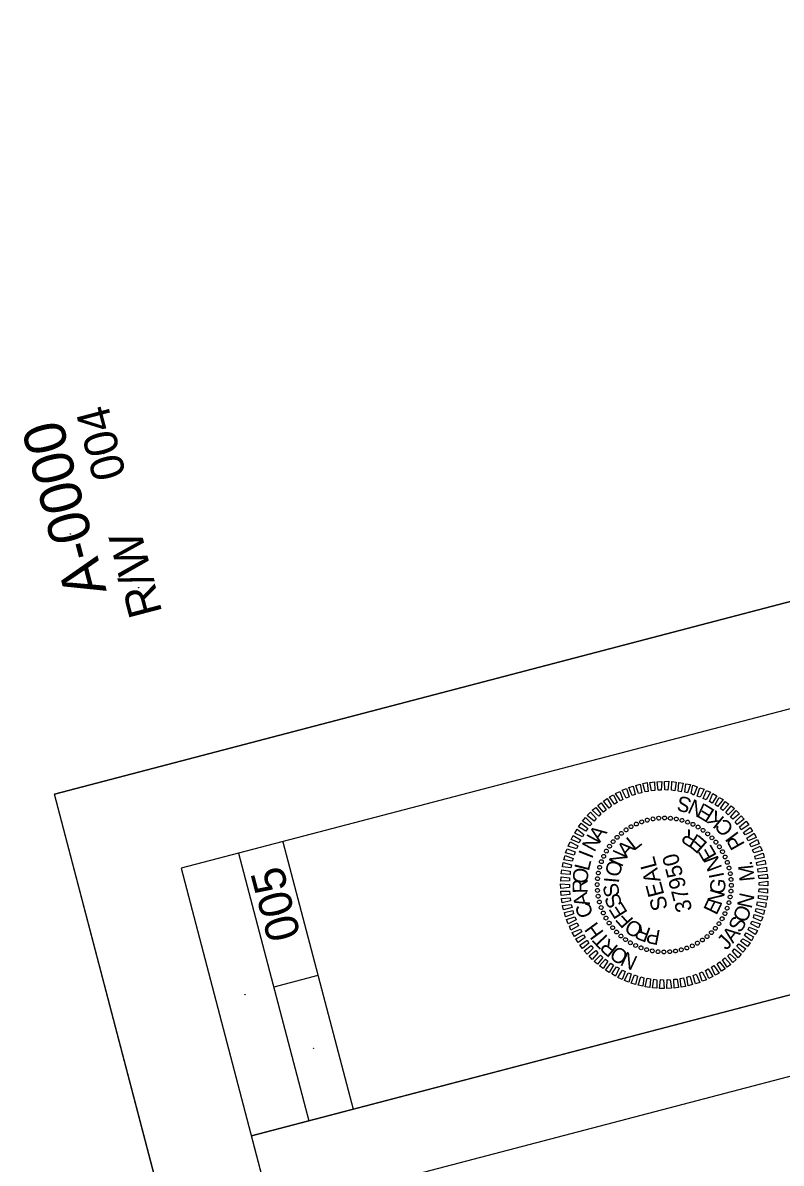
# Model space of a CAD drawing. Extents: x 1366394 to 1367903, y 879298 to 881221.
# Drawn here: x 1366396.1 to 1366670, y 880808.9 to 881221.1 of the extents above; entities that cross this region are included whole.
import ezdxf

# ---------------------------------------------------------------- set-up
doc = ezdxf.new("R2010")
doc.units = 0
for name, color, linetype in [('Exist Property Line Leader', 7, 'Continuous'), ('Exist Property Line Text', 7, 'Continuous'), ('Exist Right of Way Line', 7, 'Continuous'), ('Exist Structure Minor Footbridge Terminator', 7, 'Continuous'), ('Exist Structure Minor Pipes RCP 12 Inch', 7, 'Continuous'), ('Scratch_Level_0', 7, 'Continuous'), ('Scratch_Level_4', 7, 'Continuous')]:
    doc.layers.add(name, color=color, linetype=linetype)

msp = doc.modelspace()

# ---------------------------------------------------------------- linework, layer by layer
at = {"layer": 'Exist Property Line Leader'}
for centre in [(1366425.25, 881065.36), (1366413.25, 881036.37), (1366437.93, 881016.99)]:
    msp.add_circle(centre, 0.06, dxfattribs=at)
at = {"layer": 'Exist Property Line Text'}
for p in [(1367471.6, 881221.14), (1366838.49, 879297.82)]:
    msp.add_line(p, (1366407.53, 880942.29), dxfattribs=at)
for centre in [(1366488.35, 880898.86), (1366476.35, 880869.87), (1366501.03, 880850.49)]:
    msp.add_circle(centre, 0.06, dxfattribs=at)
at = {"layer": 'Exist Right of Way Line'}
for p, q in [((1367444.83, 881175.34), (1366453.31, 880915.52)), ((1367470.18, 881078.61), (1366478.66, 880818.79)), ((1366489.99, 880925.13), (1366515.34, 880828.4)), ((1366474.03, 880920.95), (1366499.38, 880824.22)), ((1366453.31, 880915.52), (1366865.26, 879343.61)), ((1366502.67, 880876.77), (1366486.71, 880872.58))]:
    msp.add_line(p, q, dxfattribs=at)
at = {"layer": 'Exist Structure Minor Footbridge Terminator'}
msp.add_lwpolyline([(1366869.99, 879396.08), (1366503.15, 880795.86), (1367465.82, 881048.15), (1367814.91, 879716.05)], close=True, dxfattribs=at)
at = {"layer": 'Exist Structure Minor Pipes RCP 12 Inch'}
for p, q in [((1366615.74, 880930.55), (1366615.74, 880930.55)), ((1366617.68, 880931.5), (1366617.68, 880931.5)), ((1366619.61, 880932.34), (1366619.61, 880932.34)), ((1366621.64, 880932.96), (1366621.64, 880932.96)), ((1366623.72, 880933.39), (1366623.72, 880933.39)), ((1366625.81, 880933.63), (1366625.81, 880933.63)), ((1366627.89, 880933.76), (1366627.89, 880933.76)), ((1366630.02, 880933.66), (1366630.02, 880933.66)), ((1366632.11, 880933.34), (1366632.11, 880933.34)), ((1366634.19, 880932.92), (1366634.19, 880932.92)), ((1366636.19, 880932.23), (1366636.19, 880932.23)), ((1366638.17, 880931.43), (1366638.17, 880931.43)), ((1366640, 880930.44), (1366640, 880930.44)), ((1366610.75, 880926.74), (1366610.75, 880926.74)), ((1366612.3, 880928.18), (1366612.3, 880928.18)), ((1366613.95, 880929.45), (1366613.95, 880929.45)), ((1366641.83, 880929.3), (1366641.83, 880929.3)), ((1366643.45, 880928), (1366643.45, 880928)), ((1366645.01, 880926.53), (1366645.01, 880926.53)), ((1366606.84, 880921.73), (1366606.84, 880921.73)), ((1366607.98, 880923.56), (1366607.98, 880923.56)), ((1366609.28, 880925.18), (1366609.28, 880925.18)), ((1366646.45, 880924.98), (1366646.45, 880924.98)), ((1366647.72, 880923.33), (1366647.72, 880923.33)), ((1366648.82, 880921.54), (1366648.82, 880921.54)), ((1366605.05, 880917.92), (1366605.05, 880917.92)), ((1366605.85, 880919.9), (1366605.85, 880919.9)), ((1366649.77, 880919.59), (1366649.77, 880919.59)), ((1366650.61, 880917.67), (1366650.61, 880917.67)), ((1366603.94, 880913.85), (1366603.94, 880913.85)), ((1366604.36, 880915.92), (1366604.36, 880915.92)), ((1366651.23, 880915.64), (1366651.23, 880915.64)), ((1366651.67, 880913.55), (1366651.67, 880913.55)), ((1366603.52, 880909.62), (1366603.52, 880909.62)), ((1366603.62, 880911.75), (1366603.62, 880911.75)), ((1366627.77, 880909.51), (1366627.77, 880909.51)), ((1366651.9, 880911.47), (1366651.9, 880911.47)), ((1366652.03, 880909.4), (1366652.03, 880909.4)), ((1366603.65, 880907.55), (1366603.65, 880907.55)), ((1366603.88, 880905.45), (1366603.88, 880905.45)), ((1366651.61, 880905.16), (1366651.61, 880905.16)), ((1366651.93, 880907.26), (1366651.93, 880907.26)), ((1366604.32, 880903.37), (1366604.32, 880903.37)), ((1366604.94, 880901.34), (1366604.94, 880901.34)), ((1366650.5, 880901.09), (1366650.5, 880901.09)), ((1366651.19, 880903.09), (1366651.19, 880903.09)), ((1366605.78, 880899.42), (1366605.78, 880899.42)), ((1366606.73, 880897.47), (1366606.73, 880897.47)), ((1366648.71, 880897.28), (1366648.71, 880897.28)), ((1366649.7, 880899.11), (1366649.7, 880899.11)), ((1366607.83, 880895.68), (1366607.83, 880895.68)), ((1366609.1, 880894.03), (1366609.1, 880894.03)), ((1366646.27, 880893.83), (1366646.27, 880893.83)), ((1366647.57, 880895.45), (1366647.57, 880895.45)), ((1366610.54, 880892.48), (1366610.54, 880892.48)), ((1366612.1, 880891.01), (1366612.1, 880891.01)), ((1366613.72, 880889.71), (1366613.72, 880889.71)), ((1366615.55, 880888.57), (1366615.55, 880888.57)), ((1366641.6, 880889.56), (1366641.6, 880889.56)), ((1366643.25, 880890.83), (1366643.25, 880890.83)), ((1366644.8, 880892.27), (1366644.8, 880892.27)), ((1366617.38, 880887.58), (1366617.38, 880887.58)), ((1366619.36, 880886.78), (1366619.36, 880886.78)), ((1366621.36, 880886.09), (1366621.36, 880886.09)), ((1366623.44, 880885.66), (1366623.44, 880885.66)), ((1366625.53, 880885.35), (1366625.53, 880885.35)), ((1366627.67, 880885.25), (1366627.67, 880885.25)), ((1366629.74, 880885.38), (1366629.74, 880885.38)), ((1366631.83, 880885.62), (1366631.83, 880885.62)), ((1366633.91, 880886.05), (1366633.91, 880886.05)), ((1366635.94, 880886.67), (1366635.94, 880886.67)), ((1366637.86, 880887.51), (1366637.86, 880887.51)), ((1366639.81, 880888.46), (1366639.81, 880888.46))]:
    msp.add_line(p, q, dxfattribs=at)
for points in [[(1366620.84, 880943.12), (1366620.09, 880946.17), (1366621.65, 880946.5), (1366621.99, 880943.34)], [(1366623.14, 880943.51), (1366622.58, 880946.57), (1366624.22, 880946.82), (1366624.32, 880943.6)], [(1366625.62, 880943.81), (1366625.18, 880946.79), (1366626.85, 880946.91), (1366626.7, 880943.71)], [(1366628.02, 880943.83), (1366627.81, 880946.88), (1366629.44, 880946.99), (1366629.1, 880943.73)], [(1366630.45, 880943.76), (1366630.47, 880946.88), (1366632.08, 880946.67), (1366631.56, 880943.52)], [(1366632.75, 880943.4), (1366633.01, 880946.59), (1366634.65, 880946.29), (1366633.9, 880943.22)], [(1366611.93, 880939.86), (1366610.22, 880942.54), (1366611.72, 880943.27), (1366612.83, 880940.42)], [(1366614.04, 880940.91), (1366612.54, 880943.75), (1366614.08, 880944.33), (1366615.11, 880941.41)], [(1366616.2, 880941.81), (1366614.97, 880944.73), (1366616.53, 880945.27), (1366617.29, 880942.22)], [(1366618.51, 880942.51), (1366617.52, 880945.5), (1366619.1, 880945.94), (1366619.62, 880942.83)], [(1366635.15, 880943.07), (1366635.57, 880946.05), (1366637.21, 880945.76), (1366636.19, 880942.76)], [(1366637.46, 880942.52), (1366638.13, 880945.52), (1366639.69, 880944.95), (1366638.51, 880942.01)], [(1366639.71, 880941.65), (1366640.59, 880944.6), (1366642.19, 880944.1), (1366640.77, 880941.29)], [(1366641.87, 880940.75), (1366643.01, 880943.68), (1366644.5, 880942.99), (1366642.89, 880940.33)], [(1366644.1, 880939.62), (1366645.34, 880942.52), (1366646.73, 880941.66), (1366645.05, 880939.08)], [(1366605.88, 880935.86), (1366603.72, 880938.21), (1366605.03, 880939.23), (1366606.77, 880936.61)], [(1366607.83, 880937.31), (1366605.83, 880939.81), (1366607.12, 880940.72), (1366608.67, 880938.05)], [(1366609.85, 880938.68), (1366607.95, 880941.35), (1366609.4, 880942.06), (1366610.74, 880939.28)], [(1366646.15, 880938.54), (1366647.62, 880941.16), (1366649.05, 880940.36), (1366647.05, 880937.84)], [(1366648.12, 880937.09), (1366649.79, 880939.71), (1366651.12, 880938.73), (1366648.97, 880936.37)], [(1366650.01, 880935.71), (1366651.9, 880938.1), (1366653.12, 880937.14), (1366650.85, 880934.84)], [(1366600.87, 880930.84), (1366598.28, 880932.57), (1366599.38, 880933.83), (1366601.6, 880931.65)], [(1366602.43, 880932.58), (1366599.98, 880934.55), (1366601.12, 880935.83), (1366603.18, 880933.5)], [(1366604.14, 880934.37), (1366601.79, 880936.51), (1366603.05, 880937.52), (1366604.87, 880935.17)], [(1366651.75, 880933.99), (1366653.77, 880936.42), (1366654.92, 880935.18), (1366652.55, 880933.26)], [(1366653.42, 880932.3), (1366655.61, 880934.52), (1366656.66, 880933.26), (1366654.13, 880931.4)], [(1366599.45, 880928.93), (1366596.76, 880930.49), (1366597.74, 880931.81), (1366600.2, 880929.85)], [(1366654.97, 880930.53), (1366657.33, 880932.5), (1366658.28, 880931.26), (1366655.58, 880929.45)], [(1366656.36, 880928.47), (1366658.85, 880930.32), (1366659.67, 880928.99), (1366656.95, 880927.58)], [(1366597.07, 880924.71), (1366594.12, 880925.94), (1366594.92, 880927.36), (1366597.52, 880925.79)], [(1366598.23, 880926.84), (1366595.48, 880928.22), (1366596.29, 880929.65), (1366598.78, 880927.74)], [(1366657.59, 880926.4), (1366660.24, 880928.2), (1366661.01, 880926.71), (1366658.09, 880925.49)], [(1366658.72, 880924.32), (1366661.49, 880925.9), (1366662.06, 880924.4), (1366659.18, 880923.24)], [(1366595.27, 880920.24), (1366592.11, 880921.11), (1366592.75, 880922.59), (1366595.54, 880921.42)], [(1366596.13, 880922.54), (1366593.09, 880923.54), (1366593.77, 880925.03), (1366596.53, 880923.6)], [(1366659.63, 880922.16), (1366662.46, 880923.51), (1366663.09, 880921.98), (1366660.08, 880921.09)], [(1366594.05, 880915.63), (1366590.99, 880916.03), (1366591.23, 880917.65), (1366594.28, 880916.8)], [(1366594.52, 880918.07), (1366591.52, 880918.58), (1366591.92, 880920.2), (1366594.83, 880919.11)], [(1366660.52, 880919.9), (1366663.47, 880920.98), (1366663.86, 880919.44), (1366660.78, 880918.77)], [(1366661.1, 880917.66), (1366664.12, 880918.51), (1366664.5, 880916.96), (1366661.36, 880916.53)], [(1366593.76, 880913.3), (1366590.53, 880913.54), (1366590.72, 880915), (1366593.78, 880914.46)], [(1366661.61, 880915.3), (1366664.68, 880915.96), (1366664.84, 880914.35), (1366661.74, 880914.13)], [(1366661.86, 880912.96), (1366664.96, 880913.38), (1366665.16, 880911.78), (1366662.04, 880911.8)], [(1366593.53, 880908.57), (1366590.38, 880908.18), (1366590.31, 880909.87), (1366593.49, 880909.61)], [(1366593.51, 880910.97), (1366590.43, 880910.86), (1366590.49, 880912.43), (1366593.56, 880912.04)], [(1366662.02, 880910.44), (1366665.17, 880910.83), (1366665.24, 880909.14), (1366662.06, 880909.4)], [(1366593.68, 880906.05), (1366590.59, 880905.63), (1366590.39, 880907.23), (1366593.51, 880907.21)], [(1366661.79, 880905.71), (1366665.02, 880905.47), (1366664.83, 880904.01), (1366661.77, 880904.55)], [(1366662.04, 880908.04), (1366665.12, 880908.15), (1366665.06, 880906.58), (1366661.99, 880906.97)], [(1366593.94, 880903.72), (1366590.87, 880903.05), (1366590.71, 880904.66), (1366593.81, 880904.89)], [(1366594.45, 880901.35), (1366591.43, 880900.51), (1366591.05, 880902.05), (1366594.19, 880902.48)], [(1366661.03, 880900.94), (1366664.03, 880900.42), (1366663.63, 880898.81), (1366660.72, 880899.9)], [(1366661.5, 880903.38), (1366664.56, 880902.98), (1366664.32, 880901.36), (1366661.27, 880902.21)], [(1366595.03, 880899.11), (1366592.08, 880898.03), (1366591.69, 880899.57), (1366594.77, 880900.24)], [(1366595.92, 880896.85), (1366593.09, 880895.5), (1366592.46, 880897.03), (1366595.47, 880897.93)], [(1366660.28, 880898.77), (1366663.43, 880897.9), (1366662.8, 880896.42), (1366660.01, 880897.59)], [(1366596.82, 880894.69), (1366594.06, 880893.11), (1366593.49, 880894.61), (1366596.37, 880895.77)], [(1366597.96, 880892.61), (1366595.31, 880890.81), (1366594.54, 880892.3), (1366597.46, 880893.52)], [(1366658.48, 880894.3), (1366661.43, 880893.08), (1366660.63, 880891.65), (1366658.03, 880893.22)], [(1366659.42, 880896.47), (1366662.46, 880895.47), (1366661.78, 880893.98), (1366659.02, 880895.41)], [(1366599.2, 880890.54), (1366596.71, 880888.69), (1366595.88, 880890.02), (1366598.59, 880891.43)], [(1366600.58, 880888.48), (1366598.22, 880886.51), (1366597.27, 880887.75), (1366599.97, 880889.56)], [(1366656.1, 880890.07), (1366658.79, 880888.52), (1366657.81, 880887.2), (1366655.36, 880889.16)], [(1366657.32, 880892.17), (1366660.06, 880890.79), (1366659.26, 880889.36), (1366656.77, 880891.26)], [(1366602.13, 880886.71), (1366599.94, 880884.49), (1366598.89, 880885.74), (1366601.42, 880887.61)], [(1366603.8, 880885.02), (1366601.78, 880882.59), (1366600.63, 880883.83), (1366603, 880885.75)], [(1366651.41, 880884.64), (1366653.77, 880882.5), (1366652.5, 880881.49), (1366650.68, 880883.84)], [(1366653.12, 880886.43), (1366655.57, 880884.46), (1366654.43, 880883.18), (1366652.37, 880885.52)], [(1366654.68, 880888.17), (1366657.27, 880886.44), (1366656.17, 880885.18), (1366653.95, 880887.36)], [(1366605.54, 880883.3), (1366603.65, 880880.91), (1366602.43, 880881.88), (1366604.7, 880884.17)], [(1366607.43, 880881.93), (1366605.76, 880879.3), (1366604.43, 880880.28), (1366606.58, 880882.64)], [(1366609.4, 880880.47), (1366607.93, 880877.85), (1366606.5, 880878.65), (1366608.5, 880881.17)], [(1366645.7, 880880.33), (1366647.6, 880877.66), (1366646.14, 880876.95), (1366644.81, 880879.73)], [(1366647.72, 880881.7), (1366649.72, 880879.21), (1366648.43, 880878.29), (1366646.87, 880880.96)], [(1366649.67, 880883.15), (1366651.83, 880880.8), (1366650.52, 880879.78), (1366648.78, 880882.4)], [(1366611.45, 880879.39), (1366610.21, 880876.49), (1366608.82, 880877.35), (1366610.5, 880879.93)], [(1366613.68, 880878.26), (1366612.54, 880875.34), (1366611.05, 880876.02), (1366612.66, 880878.68)], [(1366615.84, 880877.36), (1366614.96, 880874.41), (1366613.36, 880874.91), (1366614.78, 880877.72)], [(1366618.09, 880876.49), (1366617.42, 880873.5), (1366615.86, 880874.06), (1366617.04, 880877)], [(1366620.4, 880875.94), (1366619.98, 880872.96), (1366618.35, 880873.25), (1366619.36, 880876.25)], [(1366637.04, 880876.5), (1366638.03, 880873.51), (1366636.45, 880873.07), (1366635.93, 880876.18)], [(1366639.36, 880877.2), (1366640.58, 880874.28), (1366639.02, 880873.74), (1366638.27, 880876.79)], [(1366641.51, 880878.1), (1366643.01, 880875.26), (1366641.47, 880874.68), (1366640.45, 880877.6)], [(1366643.62, 880879.15), (1366645.33, 880876.47), (1366643.83, 880875.74), (1366642.72, 880878.6)], [(1366622.8, 880875.61), (1366622.54, 880872.42), (1366620.9, 880872.72), (1366621.65, 880875.78)], [(1366625.1, 880875.25), (1366625.08, 880872.14), (1366623.47, 880872.34), (1366623.98, 880875.49)], [(1366627.53, 880875.18), (1366627.74, 880872.13), (1366626.11, 880872.02), (1366626.45, 880875.28)], [(1366629.93, 880875.2), (1366630.37, 880872.22), (1366628.7, 880872.1), (1366628.85, 880875.3)], [(1366632.41, 880875.5), (1366632.97, 880872.44), (1366631.33, 880872.19), (1366631.23, 880875.42)], [(1366634.71, 880875.89), (1366635.46, 880872.84), (1366633.9, 880872.51), (1366633.56, 880875.67)]]:
    msp.add_lwpolyline(points, close=True, dxfattribs=at)
for centre, major_axis, ratio in [((1366623.7, 880933.38), (-0.117, 0.685), 0.999706), ((1366625.8, 880933.64), (-0.058, 0.693), 0.999706), ((1366627.91, 880933.72), (0.002, 0.695), 0.999706), ((1366630.02, 880933.62), (0.063, 0.693), 0.999706), ((1366632.11, 880933.33), (0.122, 0.684), 0.999707), ((1366613.99, 880929.42), (-0.394, 0.573), 0.999706), ((1366615.78, 880930.54), (-0.343, 0.605), 0.999706), ((1366617.66, 880931.51), (-0.289, 0.632), 0.999706), ((1366619.62, 880932.31), (-0.234, 0.655), 0.999706), ((1366621.63, 880932.93), (-0.176, 0.673), 0.999706), ((1366634.17, 880932.86), (0.181, 0.671), 0.999707), ((1366636.18, 880932.22), (0.239, 0.653), 0.999707), ((1366638.13, 880931.4), (0.295, 0.63), 0.999708), ((1366640, 880930.41), (0.348, 0.602), 0.999708), ((1366641.78, 880929.27), (0.4, 0.569), 0.999709), ((1366609.31, 880925.17), (-0.528, 0.452), 0.999707), ((1366610.74, 880926.72), (-0.487, 0.496), 0.999707), ((1366612.31, 880928.14), (-0.442, 0.537), 0.999707), ((1366643.45, 880927.97), (0.448, 0.532), 0.999709), ((1366645, 880926.53), (0.493, 0.491), 0.99971), ((1366646.41, 880924.97), (0.534, 0.446), 0.99971), ((1366606.87, 880921.73), (-0.599, 0.353), 0.999708), ((1366608.01, 880923.5), (-0.566, 0.404), 0.999708), ((1366647.69, 880923.29), (0.571, 0.397), 0.99971), ((1366648.82, 880921.5), (0.603, 0.346), 0.99971), ((1366605.06, 880917.91), (-0.651, 0.244), 0.999709), ((1366605.88, 880919.86), (-0.627, 0.3), 0.999709), ((1366649.78, 880919.62), (0.631, 0.291), 0.999711), ((1366650.58, 880917.66), (0.655, 0.235), 0.999711), ((1366603.95, 880913.84), (-0.684, 0.127), 0.99971), ((1366604.41, 880915.9), (-0.67, 0.186), 0.99971), ((1366651.2, 880915.64), (0.673, 0.176), 0.999711), ((1366651.65, 880913.58), (0.686, 0.116), 0.999711), ((1366603.55, 880909.64), (-0.695, 0.005), 0.99971), ((1366603.66, 880911.75), (-0.692, 0.066), 0.99971), ((1366651.91, 880911.48), (0.693, 0.056), 0.999711), ((1366652, 880909.37), (0.695, -0.005), 0.99971), ((1366603.63, 880907.52), (-0.693, -0.056), 0.999711), ((1366603.9, 880905.43), (-0.686, -0.116), 0.999711), ((1366651.6, 880905.17), (0.684, -0.127), 0.99971), ((1366651.89, 880907.26), (0.692, -0.066), 0.99971), ((1366604.35, 880903.36), (-0.673, -0.176), 0.999711), ((1366604.97, 880901.34), (-0.655, -0.235), 0.999711), ((1366650.49, 880901.09), (0.651, -0.244), 0.999709), ((1366651.14, 880903.11), (0.67, -0.186), 0.99971), ((1366605.77, 880899.39), (-0.631, -0.291), 0.999711), ((1366606.73, 880897.51), (-0.603, -0.346), 0.99971), ((1366648.68, 880897.28), (0.599, -0.353), 0.999708), ((1366649.67, 880899.15), (0.627, -0.3), 0.999709), ((1366607.86, 880895.72), (-0.571, -0.397), 0.99971), ((1366609.14, 880894.04), (-0.534, -0.446), 0.99971), ((1366610.55, 880892.47), (-0.493, -0.491), 0.99971), ((1366644.81, 880892.28), (0.487, -0.496), 0.999707), ((1366646.24, 880893.83), (0.528, -0.452), 0.999707), ((1366647.54, 880895.5), (0.566, -0.404), 0.999708), ((1366612.1, 880891.03), (-0.448, -0.532), 0.999709), ((1366613.77, 880889.74), (-0.4, -0.569), 0.999709), ((1366615.55, 880888.59), (-0.348, -0.602), 0.999708), ((1366639.77, 880888.46), (0.343, -0.605), 0.999706), ((1366641.56, 880889.59), (0.394, -0.573), 0.999706), ((1366643.24, 880890.86), (0.442, -0.537), 0.999707), ((1366617.42, 880887.61), (-0.295, -0.63), 0.999708), ((1366619.37, 880886.79), (-0.239, -0.653), 0.999707), ((1366621.38, 880886.14), (-0.181, -0.671), 0.999707), ((1366623.44, 880885.67), (-0.122, -0.684), 0.999707), ((1366625.53, 880885.39), (-0.063, -0.693), 0.999706), ((1366627.64, 880885.28), (-0.002, -0.695), 0.999706), ((1366629.75, 880885.36), (0.058, -0.693), 0.999706), ((1366631.85, 880885.63), (0.117, -0.685), 0.999706), ((1366633.92, 880886.07), (0.176, -0.673), 0.999706), ((1366635.93, 880886.7), (0.234, -0.655), 0.999706), ((1366637.89, 880887.49), (0.289, -0.632), 0.999706)]:
    msp.add_ellipse(centre, major_axis=major_axis, ratio=ratio, dxfattribs=at)
at = {"layer": 'Scratch_Level_0'}
msp.add_lwpolyline([(1366865.26, 879343.61), (1366478.66, 880818.79), (1367470.18, 881078.63), (1367856.77, 879603.45)], close=True, dxfattribs=at)
at = {"layer": 'Scratch_Level_4'}
msp.add_lwpolyline([(1366838.49, 879297.82), (1366407.53, 880942.29), (1367471.6, 881221.14), (1367902.56, 879576.68)], close=True, dxfattribs=at)

# ---------------------------------------------------------------- texts
at = {"layer": 'Exist Property Line Leader'}
for s, height, p in [('004', 12, (1366433.48, 881057.63)), ('A-0000', 15, (1366426.4, 881015.76)), ('R/W', 12, (1366446.48, 881008.02)), ('005', 12.003, (1366496.53, 880891.09))]:
    msp.add_text(s, height=height, rotation=104.6851, dxfattribs=at).set_placement(p)
at = {"layer": 'Exist Structure Minor Pipes RCP 12 Inch'}
for s, height, rotation, p in [('S', 5.46, 164.7452, (1366638.03, 880940.59)), ('N', 5.46, 155.468, (1366642.91, 880938.53)), ('E', 5.46, 148.3514, (1366646.38, 880936.43)), ('K', 5.46, 140.5331, (1366649.87, 880933.65)), ('A', 5.45, 54.3023, (1366604.52, 880924.64)), ('R', 5.45, 148.1665, (1366640.6, 880927.24)), ('C', 5.46, 131.9391, (1366653.23, 880930.08)), ('N', 5.45, 61.5041, (1366602.54, 880921.12)), ('L', 5.45, 38.086, (1366616.87, 880921.73)), ('E', 5.45, 138.8091, (1366643.71, 880924.56)), ('I', 5.46, 126.7985, (1366654.98, 880927.71)), ('P', 5.46, 119.6819, (1366657.02, 880924.2)), ('I', 5.45, 68.7053, (1366601.67, 880918.72)), ('N', 5.45, 66.1618, (1366612.5, 880915.69)), ('A', 5.45, 47.4454, (1366614.17, 880919.02)), ('E', 5.45, 120.0968, (1366646.91, 880920.14)), ('L', 5.45, 75.906, (1366600.49, 880914.32)), ('O', 5.45, 75.5187, (1366611.51, 880912.05)), ('SEAL', 5.793, 104.8532, (1366629.16, 880901.02)), ('37950', 5.794, 104.6851, (1366637.95, 880900.5)), ('N', 5.44, 110.7415, (1366648.76, 880915.69)), ('.', 5.46, 105.4395, (1366659.74, 880916.56)), ('O', 5.44, 83.1063, (1366599.92, 880909.75)), ('I', 5.44, 101.3863, (1366649.49, 880912.54)), ('M', 5.46, 95.6821, (1366660.47, 880911.04)), ('R', 5.45, 90.3062, (1366600.1, 880906.44)), ('S', 5.44, 103.5855, (1366611.86, 880905.83)), ('I', 5.45, 84.8748, (1366611.38, 880910.01)), ('G', 5.45, 82.6754, (1366649.44, 880905.95)), ('A', 5.44, 104.7054, (1366601.01, 880902.48)), ('S', 5.44, 112.9407, (1366612.84, 880902.5)), ('N', 5.45, 73.3191, (1366648.34, 880901.83)), ('N', 5.46, 77.4417, (1366659.31, 880900.73)), ('C', 5.44, 111.905, (1366602.32, 880898.89)), ('E', 5.45, 122.2961, (1366614.72, 880899.56)), ('E', 5.45, 63.9621, (1366646.61, 880898.33)), ('O', 5.46, 67.6659, (1366657.36, 880895.5)), ('F', 5.44, 131.6521, (1366616.95, 880896.98)), ('S', 5.46, 60.42, (1366655.35, 880891.88)), ('H', 5.45, 126.3045, (1366606.16, 880892.34)), ('O', 5.45, 150.3663, (1366620.55, 880894.68)), ('R', 5.45, 159.7247, (1366623.29, 880893.69)), ('P', 5.45, 169.0839, (1366626.68, 880893.04)), ('A', 5.46, 52.2692, (1366652.58, 880888.15)), ('T', 5.45, 133.5048, (1366608.54, 880889.75)), ('R', 5.45, 140.7056, (1366611.48, 880887.17)), ('J', 5.46, 46.2588, (1366650.2, 880885.67)), ('O', 5.45, 147.9068, (1366615.26, 880884.77)), ('N', 5.45, 155.1085, (1366618.56, 880883.39))]:
    msp.add_text(s, height=height, rotation=rotation, dxfattribs=at).set_placement(p)

doc.saveas('drawing.dxf')
